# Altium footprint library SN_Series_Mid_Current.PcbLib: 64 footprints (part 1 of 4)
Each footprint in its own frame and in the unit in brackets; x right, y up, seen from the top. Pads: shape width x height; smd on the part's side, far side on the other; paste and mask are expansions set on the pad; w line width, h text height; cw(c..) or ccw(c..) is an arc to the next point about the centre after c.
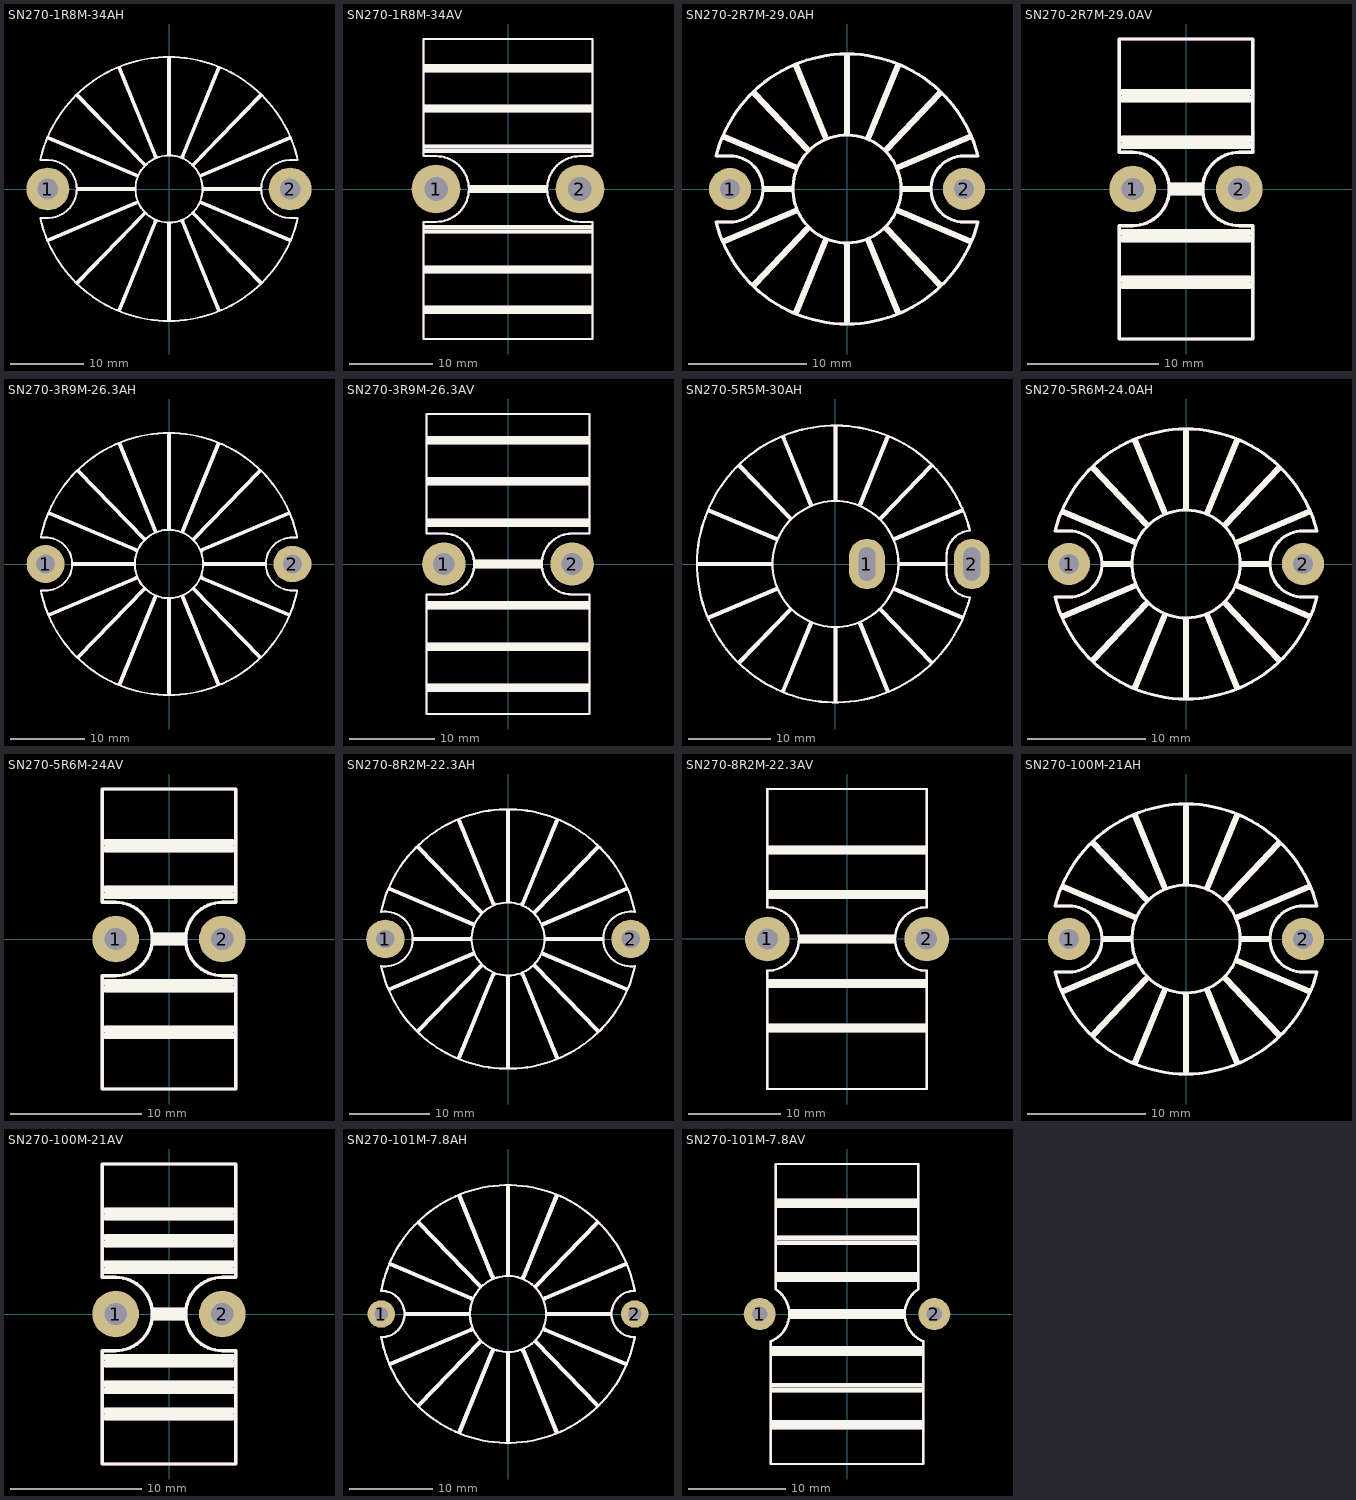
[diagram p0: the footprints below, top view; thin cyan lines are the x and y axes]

## PCBComponent_1 [mil]

## SN270-1R8M-34AH [mil]
pads (2):
  round 230 hole 111: 1(-650,0) 2(650,0)
Top Overlay:
  circle w10: c0,0 r180
  lines w10: -691.27,-155.29 ccw(c0,0) 691.27,-155.29 ; -691.27,-155 -650,-155 ccw(c-650,0) -650,155 -691.27,155 ; -691.27,155.29 cw(c0,0) 691.27,155.29 ; 691.27,-155 650,-155 cw(c650,0) 650,155 691.27,155
  lines w19.68: -649.49,-275.21 -175.3,-74.28 ; -649.49,275.21 -175.3,74.28 ; -490.97,-502.26 -132.5,-132.5 ; -490.97,502.26 -132.5,132.5 ; -490,0 -185,0 ; -267.76,-650.53 -72.46,-173.99 ; -267.76,650.53 -72.46,173.99 ; 0,-700 0,-185 ; 0,185 0,700 ; 72.46,-173.99 267.76,-650.53 ; 72.46,173.99 267.76,650.53 ; 132.5,-132.5 490.97,-502.26 ; 132.5,132.5 490.97,502.26 ; 175.3,-74.28 649.49,-275.21 ; 175.3,74.28 649.49,275.21 ; 185,0 490,0
Mechanical 29:
  circle w10: c0,0 r180
  lines w10: -691.27,-155.29 ccw(c0,0) 691.27,-155.29 ; -691.27,-155 -650,-155 ccw(c-650,0) -650,155 -691.27,155 ; -691.27,155.29 cw(c0,0) 691.27,155.29 ; 691.27,-155 650,-155 cw(c650,0) 650,155 691.27,155
  lines w19.68: -649.49,-275.21 -175.3,-74.28 ; -649.49,275.21 -175.3,74.28 ; -490.97,-502.26 -132.5,-132.5 ; -490.97,502.26 -132.5,132.5 ; -490,0 -185,0 ; -267.76,-650.53 -72.46,-173.99 ; -267.76,650.53 -72.46,173.99 ; 0,-700 0,-185 ; 0,185 0,700 ; 72.46,-173.99 267.76,-650.53 ; 72.46,173.99 267.76,650.53 ; 132.5,-132.5 490.97,-502.26 ; 132.5,132.5 490.97,502.26 ; 175.3,-74.28 649.49,-275.21 ; 175.3,74.28 649.49,275.21 ; 185,0 490,0
  text "'.Designator'" at -290,145.15 h400

## SN270-1R8M-34AV [mil]
pads (2):
  round 230 hole 111: 1(-340,0) 2(340,0)
Top Overlay:
  lines w10: -400,-708.5 -400,-155 -340,-155 ccw(c-340,0) -340,155 -400,155 -400,708.5 400,708.5 400,155 340,155 ccw(c340,0) 340,-155 400,-155 400,-708.5 -400,-708.5
  lines w19.68: -395,-580 395,-580 ; -395,-560 395,-560 ; -395,-390 395,-390 ; -395,-370 395,-370 ; -395,-200 395,-200 ; -395,-180 395,-180 ; -395,180 395,180 ; -395,200 395,200 ; -395,370 395,370 ; -395,390 395,390 ; -395,560 395,560 ; -395,580 395,580 ; -180,-10 180,-10 ; -180,10 180,10
Mechanical 29:
  lines w10: -400,-708.5 -400,-155 -340,-155 ccw(c-340,0) -340,155 -400,155 -400,708.5 400,708.5 400,155 340,155 ccw(c340,0) 340,-155 400,-155 400,-708.5 -400,-708.5
  lines w19.68: -395,-580 395,-580 ; -395,-560 395,-560 ; -395,-390 395,-390 ; -395,-370 395,-370 ; -395,-200 395,-200 ; -395,-180 395,-180 ; -395,180 395,180 ; -395,200 395,200 ; -395,370 395,370 ; -395,390 395,390 ; -395,560 395,560 ; -395,580 395,580 ; -180,-10 180,-10 ; -180,10 180,10
  text "'.Designator'" at -1750,-64.85 h400

## SN270-2R7M-29.0AH [mil]
pads (2):
  round 140 hole 67: 1(-390,0) 2(390,0)
Top Overlay:
  circle w10: c0,0 r180
  lines w10: -436.35,-110 ccw(c0,0) 436.35,-110 390,-110 cw(c390,0) 390,110 436.4,109.8 ccw(c0,0) -436.35,110 -390,110 cw(c-390,0) -390,-110 -436.35,-110
  lines w19.68: -410.1,-173.77 -171.07,-72.49 ; -410.1,173.77 -171.07,72.49 ; -307.74,-317.75 -132.5,-132.5 ; -307.74,317.75 -132.5,132.5 ; -275,0 -185,0 ; -169.16,-409.95 -72.46,-173.99 ; -169.16,409.95 -72.46,173.99 ; 0,-440 0,-185 ; 0,185 0,440 ; 72.46,-173.99 169.16,-409.95 ; 72.46,173.99 169.16,409.95 ; 132.5,-132.5 307.74,-317.75 ; 132.5,132.5 307.74,317.75 ; 171.07,-72.49 410.1,-173.77 ; 171.07,72.49 410.1,173.77 ; 185,0 275,0
Mechanical 29:
  circle w10: c0,0 r180
  lines w10: -436.35,-110 ccw(c0,0) 436.35,-110 390,-110 cw(c390,0) 390,110 436.4,109.8 ccw(c0,0) -436.35,110 -390,110 cw(c-390,0) -390,-110 -436.35,-110
  lines w19.68: -410.1,-173.77 -171.07,-72.49 ; -410.1,173.77 -171.07,72.49 ; -307.74,-317.75 -132.5,-132.5 ; -307.74,317.75 -132.5,132.5 ; -275,0 -185,0 ; -169.16,-409.95 -72.46,-173.99 ; -169.16,409.95 -72.46,173.99 ; 0,-440 0,-185 ; 0,185 0,440 ; 72.46,-173.99 169.16,-409.95 ; 72.46,173.99 169.16,409.95 ; 132.5,-132.5 307.74,-317.75 ; 132.5,132.5 307.74,317.75 ; 171.07,-72.49 410.1,-173.77 ; 171.07,72.49 410.1,173.77 ; 185,0 275,0
  text "'.Designator'" at -1750,-64.85 h400

## SN270-2R7M-29.0AV [mil]
pads (2):
  round 140 hole 67: 1(-160,0) 2(160,0)
Top Overlay:
  lines w10: -200,-450 -200,-110 -160,-110 ccw(c-160,0) -160,110 -200,110 -200,450 200,450 200,110 160,110 ccw(c160,0) 160,-110 200,-110 200,-450 -200,-450
  lines w19.68: -190,-290 190,-290 ; -190,-270 190,-270 ; -190,-150 190,-150 ; -190,-130 190,-130 ; -190,130 190,130 ; -190,150 190,150 ; -190,270 190,270 ; -190,290 190,290 ; -45,-10 45,-10 ; -45,10 45,10
Mechanical 29:
  lines w10: -200,-450 -200,-110 -160,-110 ccw(c-160,0) -160,110 -200,110 -200,450 200,450 200,110 160,110 ccw(c160,0) 160,-110 200,-110 200,-450 -200,-450
  lines w19.68: -190,-290 190,-290 ; -190,-270 190,-270 ; -190,-150 190,-150 ; -190,-130 190,-130 ; -190,130 190,130 ; -190,150 190,150 ; -190,270 190,270 ; -190,290 190,290 ; -45,-10 45,-10 ; -45,10 45,10
  text "'.Designator'" at -1750,-64.85 h400

## SN270-3R9M-26.3AH [mil]
pads (2):
  round 200 hole 99: 1(-650,0)
  oval 200x190 hole 99: 2(650,0)
Top Overlay:
  circle w10: c0,0 r180
  lines w10: -675.64,-140.04 ccw(c0,0) 675.64,-140.04 ; -675.63,140.1 cw(c0,0) 675.63,140.1 ; -675.46,-140 -650,-140 ccw(c-650,0) -650,140 -675.16,140 ; 675.16,140 650,140 ccw(c650,0) 650,-140 675.46,-140
  lines w19.68: -631.08,-267.41 -175.3,-74.28 ; -631.08,267.41 -175.3,74.28 ; -505,0 -185,0 ; -477.05,-487.9 -132.5,-132.5 ; -477.05,487.9 -132.5,132.5 ; -260.17,-632.02 -72.46,-173.99 ; -260.17,632.02 -72.46,173.99 ; 0,-680 0,-185 ; 0,185 0,680 ; 72.46,-173.99 260.17,-632.02 ; 72.46,173.99 260.17,632.02 ; 132.5,-132.5 477.05,-487.9 ; 132.5,132.5 477.05,487.9 ; 175.3,-74.28 631.08,-267.41 ; 175.3,74.28 631.08,267.41 ; 185,0 505,0
Mechanical 29:
  circle w10: c0,0 r180
  lines w10: -675.64,-140.04 ccw(c0,0) 675.64,-140.04 ; -675.63,140.1 cw(c0,0) 675.63,140.1 ; -675.46,-140 -650,-140 ccw(c-650,0) -650,140 -675.16,140 ; 675.16,140 650,140 ccw(c650,0) 650,-140 675.46,-140
  lines w19.68: -631.08,-267.41 -175.3,-74.28 ; -631.08,267.41 -175.3,74.28 ; -505,0 -185,0 ; -477.05,-487.9 -132.5,-132.5 ; -477.05,487.9 -132.5,132.5 ; -260.17,-632.02 -72.46,-173.99 ; -260.17,632.02 -72.46,173.99 ; 0,-680 0,-185 ; 0,185 0,680 ; 72.46,-173.99 260.17,-632.02 ; 72.46,173.99 260.17,632.02 ; 132.5,-132.5 477.05,-487.9 ; 132.5,132.5 477.05,487.9 ; 175.3,-74.28 631.08,-267.41 ; 175.3,74.28 631.08,267.41 ; 185,0 505,0
  text "'.Designator'" at -290,145.15 h400

## SN270-3R9M-26.3AV [mil]
pads (2):
  round 200 hole 99: 1(-295,0) 2(295,0)
Top Overlay:
  lines w10: -375,-690 375,-690 375,-140 295,-140 cw(c295,0) 295,140 375,140 375,690 -375,690 -375,140 -295,140 cw(c-295,0) -295,-140 -375,-140 -375,-690
  lines w19.68: -370,-580 370,-580 ; -370,-560 370,-560 ; -370,-390 370,-390 ; -370,-370 370,-370 ; -370,-200 370,-200 ; -370,-180 370,-180 ; -370,180 370,180 ; -370,200 370,200 ; -370,370 370,370 ; -370,390 370,390 ; -370,560 370,560 ; -370,580 370,580 ; -150,-10 150,-10 ; -150,10 150,10
Mechanical 29:
  lines w10: -375,-690 375,-690 375,-140 295,-140 cw(c295,0) 295,140 375,140 375,690 -375,690 -375,140 -295,140 cw(c-295,0) -295,-140 -375,-140 -375,-690
  lines w19.68: -370,-580 370,-580 ; -370,-560 370,-560 ; -370,-390 370,-390 ; -370,-370 370,-370 ; -370,-200 370,-200 ; -370,-180 370,-180 ; -370,180 370,180 ; -370,200 370,200 ; -370,370 370,370 ; -370,390 370,390 ; -370,560 370,560 ; -370,580 370,580 ; -150,-10 150,-10 ; -150,10 150,10
  text "'.Designator'" at -1750,-64.85 h400

## SN270-5R5M-30AH [mil]
pads (2):
  oval 170x240 hole 80 slot 160 at 90 deg: 1(150,0) 2(650,0)
Top Overlay:
  circle w10: c0,0 r300
  lines w10: 639.54,-159.54 cw(c650,-40) 530,-40 530,40 cw(c650,40) 639.54,159.54 ; 640.38,-159.74 cw(c0,0) -646.19,-134.29 cw(c0,0) 640.38,159.74
  lines w19.68: -655,0 -305,0 ; -603.45,-255.7 -280.49,-118.85 ; -603.45,255.7 -280.49,118.85 ; -456.17,-466.36 -216.2,-218.84 ; -456.17,466.36 -216.2,218.84 ; -248.8,-604.26 -116.49,-281.44 ; -248.8,604.26 -116.49,281.44 ; 0,305 0,650 ; 116.49,-281.44 248.8,-604.26 ; 116.49,281.44 248.8,604.26 ; 216.2,-218.84 456.17,-466.36 ; 216.2,218.84 456.17,466.36 ; 280.49,-118.85 603.45,-255.7 ; 280.49,118.85 603.45,255.7 ; 305,0 525,0 ; 0,-650 0,-305 0,-650
Mechanical 29:
  circle w10: c0,0 r300
  lines w10: 639.54,-159.54 cw(c650,-40) 530,-40 530,40 cw(c650,40) 639.54,159.54 ; 640.38,-159.74 cw(c0,0) -646.19,-134.29 cw(c0,0) 640.38,159.74
  lines w19.68: -655,0 -305,0 ; -603.45,-255.7 -280.49,-118.85 ; -603.45,255.7 -280.49,118.85 ; -456.17,-466.36 -216.2,-218.84 ; -456.17,466.36 -216.2,218.84 ; -248.8,-604.26 -116.49,-281.44 ; -248.8,604.26 -116.49,281.44 ; 0,305 0,650 ; 116.49,-281.44 248.8,-604.26 ; 116.49,281.44 248.8,604.26 ; 216.2,-218.84 456.17,-466.36 ; 216.2,218.84 456.17,466.36 ; 280.49,-118.85 603.45,-255.7 ; 280.49,118.85 603.45,255.7 ; 305,0 525,0 ; 0,-650 0,-305 0,-650
  text "'.Designator'" at -290,145.15 h400

## SN270-5R6M-24.0AH [mil]
pads (2):
  round 140 hole 67: 1(-390,0) 2(390,0)
Top Overlay:
  circle w10: c0,0 r180
  lines w10: -436.35,-110 ccw(c0,0) 436.35,-110 390,-110 cw(c390,0) 390,110 436.4,109.8 ccw(c0,0) -436.35,110 -390,110 cw(c-390,0) -390,-110 -436.35,-110
  lines w19.68: -410.1,-173.77 -171.07,-72.49 ; -410.1,173.77 -171.07,72.49 ; -307.74,-317.75 -132.5,-132.5 ; -307.74,317.75 -132.5,132.5 ; -275,0 -185,0 ; -169.16,-409.95 -72.46,-173.99 ; -169.16,409.95 -72.46,173.99 ; 0,-440 0,-185 ; 0,185 0,440 ; 72.46,-173.99 169.16,-409.95 ; 72.46,173.99 169.16,409.95 ; 132.5,-132.5 307.74,-317.75 ; 132.5,132.5 307.74,317.75 ; 171.07,-72.49 410.1,-173.77 ; 171.07,72.49 410.1,173.77 ; 185,0 275,0
Mechanical 29:
  circle w10: c0,0 r180
  lines w10: -436.35,-110 ccw(c0,0) 436.35,-110 390,-110 cw(c390,0) 390,110 436.4,109.8 ccw(c0,0) -436.35,110 -390,110 cw(c-390,0) -390,-110 -436.35,-110
  lines w19.68: -410.1,-173.77 -171.07,-72.49 ; -410.1,173.77 -171.07,72.49 ; -307.74,-317.75 -132.5,-132.5 ; -307.74,317.75 -132.5,132.5 ; -275,0 -185,0 ; -169.16,-409.95 -72.46,-173.99 ; -169.16,409.95 -72.46,173.99 ; 0,-440 0,-185 ; 0,185 0,440 ; 72.46,-173.99 169.16,-409.95 ; 72.46,173.99 169.16,409.95 ; 132.5,-132.5 307.74,-317.75 ; 132.5,132.5 307.74,317.75 ; 171.07,-72.49 410.1,-173.77 ; 171.07,72.49 410.1,173.77 ; 185,0 275,0
  text "'.Designator'" at -1750,-64.85 h400

## SN270-5R6M-24AV [mil]
pads (2):
  round 140 hole 67: 1(-160,0) 2(160,0)
Top Overlay:
  lines w10: -200,-450 200,-450 200,-110 160,-110 cw(c160,0) 160,110 200,110 200,450 -200,450 -200,110 -160,110 cw(c-160,0) -160,-110 -200,-110 -200,-450
  lines w19.68: -190,-290 190,-290 ; -190,-270 190,-270 ; -190,-150 190,-150 ; -190,-130 190,-130 ; -190,130 190,130 ; -190,150 190,150 ; -190,270 190,270 ; -190,290 190,290 ; -45,-10 45,-10 ; -45,10 45,10
Mechanical 29:
  lines w10: -200,-450 200,-450 200,-110 160,-110 cw(c160,0) 160,110 200,110 200,450 -200,450 -200,110 -160,110 cw(c-160,0) -160,-110 -200,-110 -200,-450
  lines w19.68: -190,-290 190,-290 ; -190,-270 190,-270 ; -190,-150 190,-150 ; -190,-130 190,-130 ; -190,130 190,130 ; -190,150 190,150 ; -190,270 190,270 ; -190,290 190,290 ; -45,-10 45,-10 ; -45,10 45,10
  text "'.Designator'" at -1750,-64.85 h400

## SN270-8R2M-22.3AH [mil]
pads (2):
  round 190 hole 90: 1(-605,0) 2(605,0)
Top Overlay:
  circle w10: c0,0 r180
  lines w10: -625.94,-133.4 ccw(c0,0) 625.9,-133.61 ; -625.9,133.6 cw(c0,0) 625.9,133.6 ; -625.86,-133.38 ccw(c-605,0) -625.28,133.47 ; 625.28,133.47 ccw(c605,0) 625.86,-133.38
  lines w19.68: -585.04,-247.9 -175.3,-74.28 ; -585.04,247.9 -175.3,74.28 ; -465,0 -185,0 ; -442.25,-452 -132.5,-132.5 ; -442.25,452 -132.5,132.5 ; -241.21,-585.75 -72.46,-173.99 ; -241.21,585.75 -72.46,173.99 ; 0,-630 0,-185 ; 0,185 0,630 ; 72.46,-173.99 241.21,-585.75 ; 72.46,173.99 241.21,585.75 ; 132.5,-132.5 442.25,-452 ; 132.5,132.5 442.25,452 ; 175.3,-74.28 585.04,-247.9 ; 175.3,74.28 585.04,247.9 ; 185,0 465,0
Mechanical 29:
  circle w10: c0,0 r180
  lines w10: -625.94,-133.4 ccw(c0,0) 625.9,-133.61 ; -625.9,133.6 cw(c0,0) 625.9,133.6 ; -625.86,-133.38 ccw(c-605,0) -625.28,133.47 ; 625.28,133.47 ccw(c605,0) 625.86,-133.38
  lines w19.68: -585.04,-247.9 -175.3,-74.28 ; -585.04,247.9 -175.3,74.28 ; -465,0 -185,0 ; -442.25,-452 -132.5,-132.5 ; -442.25,452 -132.5,132.5 ; -241.21,-585.75 -72.46,-173.99 ; -241.21,585.75 -72.46,173.99 ; 0,-630 0,-185 ; 0,185 0,630 ; 72.46,-173.99 241.21,-585.75 ; 72.46,173.99 241.21,585.75 ; 132.5,-132.5 442.25,-452 ; 132.5,132.5 442.25,452 ; 175.3,-74.28 585.04,-247.9 ; 175.3,74.28 585.04,247.9 ; 185,0 465,0
  text "'.Designator'" at -290,145.15 h400

## SN270-8R2M-22.3AV [mil]
pads (2):
  round 190 hole 90: 1(-340,0) 2(340,0)
Top Overlay:
  lines w10: -340,-640 -340,-135 ccw(c-340,0) -340,135 -340,640 340,640 340,135 ccw(c340,0) 340,-135 340,-640 -340,-640
  lines w19.68: -335,-390 335,-390 ; -335,-370 335,-370 ; -335,-200 335,-200 ; -335,-180 335,-180 ; -335,180 335,180 ; -335,200 335,200 ; -335,370 335,370 ; -335,390 335,390 ; -200,-10 200,-10 ; -200,10 200,10
Mechanical 29:
  lines w10: -340,-640 -340,-135 ccw(c-340,0) -340,135 -340,640 340,640 340,135 ccw(c340,0) 340,-135 340,-640 -340,-640
  lines w19.68: -335,-390 335,-390 ; -335,-370 335,-370 ; -335,-200 335,-200 ; -335,-180 335,-180 ; -335,180 335,180 ; -335,200 335,200 ; -335,370 335,370 ; -335,390 335,390 ; -200,-10 200,-10 ; -200,10 200,10
  text "'.Designator'" at -1750,-64.85 h400

## SN270-100M-21AH [mil]
pads (2):
  round 140 hole 67: 1(-390,0) 2(390,0)
Top Overlay:
  circle w10: c0,0 r180
  lines w10: -436.35,-110 ccw(c0,0) 436.35,-110 390,-110 cw(c390,0) 390,110 436.4,109.8 ccw(c0,0) -436.35,110 -390,110 cw(c-390,0) -390,-110 -436.35,-110
  lines w19.68: -410.1,-173.77 -171.07,-72.49 ; -410.1,173.77 -171.07,72.49 ; -307.74,-317.75 -132.5,-132.5 ; -307.74,317.75 -132.5,132.5 ; -275,0 -185,0 ; -169.16,-409.95 -72.46,-173.99 ; -169.16,409.95 -72.46,173.99 ; 0,-440 0,-185 ; 0,185 0,440 ; 72.46,-173.99 169.16,-409.95 ; 72.46,173.99 169.16,409.95 ; 132.5,-132.5 307.74,-317.75 ; 132.5,132.5 307.74,317.75 ; 171.07,-72.49 410.1,-173.77 ; 171.07,72.49 410.1,173.77 ; 185,0 275,0
Mechanical 29:
  circle w10: c0,0 r180
  lines w10: -436.35,-110 ccw(c0,0) 436.35,-110 390,-110 cw(c390,0) 390,110 436.4,109.8 ccw(c0,0) -436.35,110 -390,110 cw(c-390,0) -390,-110 -436.35,-110
  lines w19.68: -410.1,-173.77 -171.07,-72.49 ; -410.1,173.77 -171.07,72.49 ; -307.74,-317.75 -132.5,-132.5 ; -307.74,317.75 -132.5,132.5 ; -275,0 -185,0 ; -169.16,-409.95 -72.46,-173.99 ; -169.16,409.95 -72.46,173.99 ; 0,-440 0,-185 ; 0,185 0,440 ; 72.46,-173.99 169.16,-409.95 ; 72.46,173.99 169.16,409.95 ; 132.5,-132.5 307.74,-317.75 ; 132.5,132.5 307.74,317.75 ; 171.07,-72.49 410.1,-173.77 ; 171.07,72.49 410.1,173.77 ; 185,0 275,0
  text "'.Designator'" at -1750,-64.85 h400

## SN270-100M-21AV [mil]
pads (2):
  round 140 hole 67: 1(-160,0) 2(160,0)
Top Overlay:
  lines w10: -200,-450 200,-450 200,-110 160,-110 cw(c160,0) 160,110 200,110 200,450 -200,450 -200,110 -160,110 cw(c-160,0) -160,-110 -200,-110 -200,-450
  lines w19.68: -190,-310 190,-310 ; -190,-290 190,-290 ; -190,-230 190,-230 ; -190,-210 190,-210 ; -190,-150 190,-150 ; -190,-130 190,-130 ; -190,130 190,130 ; -190,150 190,150 ; -190,210 190,210 ; -190,230 190,230 ; -190,290 190,290 ; -190,310 190,310 ; -45,-10 45,-10 ; -45,10 45,10
Mechanical 29:
  lines w10: -200,-450 200,-450 200,-110 160,-110 cw(c160,0) 160,110 200,110 200,450 -200,450 -200,110 -160,110 cw(c-160,0) -160,-110 -200,-110 -200,-450
  lines w19.68: -190,-310 190,-310 ; -190,-290 190,-290 ; -190,-230 190,-230 ; -190,-210 190,-210 ; -190,-150 190,-150 ; -190,-130 190,-130 ; -190,130 190,130 ; -190,150 190,150 ; -190,210 190,210 ; -190,230 190,230 ; -190,290 190,290 ; -190,310 190,310 ; -45,-10 45,-10 ; -45,10 45,10
  text "'.Designator'" at -1750,-64.85 h400

## SN270-101M-7.8AH [mil]
pads (2):
  round 130 hole 62: 1(-600,0) 2(600,0)
Top Overlay:
  circle w10: c0,0 r180
  lines w10: -599.99,-110.03 ccw(c0,0) 599.83,-110.9 ; -600,-110 ccw(c-600,0) -600,110 ; -599.99,110.03 cw(c0,0) 599.84,110.89 ; 600,-110 cw(c600,0) 600,110
  lines w19.68: -557.42,-236.19 -175.3,-74.28 ; -557.42,236.19 -175.3,74.28 ; -485,0 -185,0 ; -421.36,-430.46 -132.5,-132.5 ; -421.36,430.46 -132.5,132.5 ; -229.83,-557.99 -72.46,-173.99 ; -229.83,557.99 -72.46,173.99 ; 0,-600 0,-185 ; 0,185 0,600 ; 72.46,-173.99 229.83,-557.99 ; 72.46,173.99 229.83,557.99 ; 132.5,-132.5 421.36,-430.46 ; 132.5,132.5 421.36,430.46 ; 175.3,-74.28 557.42,-236.19 ; 175.3,74.28 557.42,236.19 ; 185,0 485,0
Mechanical 29:
  circle w10: c0,0 r180
  lines w10: -599.99,-110.03 ccw(c0,0) 599.83,-110.9 ; -600,-110 ccw(c-600,0) -600,110 ; -599.99,110.03 cw(c0,0) 599.84,110.89 ; 600,-110 cw(c600,0) 600,110
  lines w19.68: -557.42,-236.19 -175.3,-74.28 ; -557.42,236.19 -175.3,74.28 ; -485,0 -185,0 ; -421.36,-430.46 -132.5,-132.5 ; -421.36,430.46 -132.5,132.5 ; -229.83,-557.99 -72.46,-173.99 ; -229.83,557.99 -72.46,173.99 ; 0,-600 0,-185 ; 0,185 0,600 ; 72.46,-173.99 229.83,-557.99 ; 72.46,173.99 229.83,557.99 ; 132.5,-132.5 421.36,-430.46 ; 132.5,132.5 421.36,430.46 ; 175.3,-74.28 557.42,-236.19 ; 175.3,74.28 557.42,236.19 ; 185,0 485,0
  text "'.Designator'" at -290,145.15 h400

## SN270-101M-7.8AV [mil]
pads (2):
  round 130 hole 62: 1(-355,0) 2(355,0)
Top Overlay:
  lines w10: -290.53,101.21 cw(c-355,0) -310,-111.24 -310,-610 310,-610 310,-111.98 ; -290,102.03 -290,610 290,610 290,102.03 ; 290.53,101.21 ccw(c355,0) 310.26,-111.35
  lines w19.68: -305,-460 305,-460 ; -305,-440 305,-440 ; -305,-310 302,-310 ; -305,-290 305,-290 ; -305,-160 303,-160 ; -305,-140 303,-140 ; -285,140 285,140 ; -285,160 285,160 ; -285,290 285,290 ; -285,310 285,310 ; -285,440 285,440 ; -285,460 285,460 ; -230,-10 230,-10 ; -230,10 230,10
Mechanical 29:
  lines w10: -290.53,101.21 cw(c-355,0) -310,-111.24 -310,-610 310,-610 310,-111.98 ; -290,102.03 -290,610 290,610 290,102.03 ; 290.53,101.21 ccw(c355,0) 310.26,-111.35
  lines w19.68: -305,-460 305,-460 ; -305,-440 305,-440 ; -305,-310 302,-310 ; -305,-290 305,-290 ; -305,-160 303,-160 ; -305,-140 303,-140 ; -285,140 285,140 ; -285,160 285,160 ; -285,290 285,290 ; -285,310 285,310 ; -285,440 285,440 ; -285,460 285,460 ; -230,-10 230,-10 ; -230,10 230,10
  text "'.Designator'" at -1750,-64.85 h400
